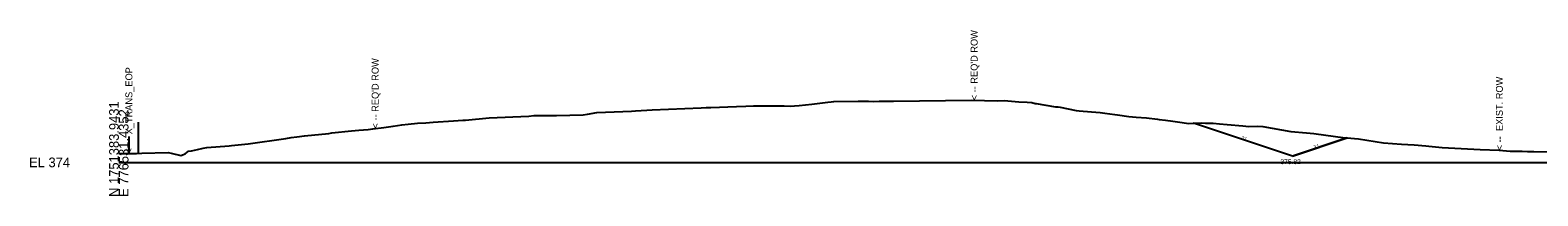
# Model space of a CAD drawing. Extents: x 776426 to 854588, y 1736205 to 1756790.
# Drawn here: x 805845.1 to 806281.9, y 1741705.1 to 1741753.1 of the extents above; entities that cross this region are included whole.
import ezdxf

# ---------------------------------------------------------------- set-up
doc = ezdxf.new("R2010")
doc.units = 0
for name, color, linetype in [('DTM CONTOURS_MAJOR_TX', 7, 'Continuous'), ('DTM_X_FLOW_ARROWS', 7, 'Continuous'), ('TRANS_EOP_PAVED', 7, 'Continuous'), ('X_TRANS_EOP', 7, 'Continuous'), ('XS_M_SHAPES_EARTHWORK', 7, 'Continuous'), ('XS_P_FINISHED_GRADE', 7, 'Continuous'), ('XS_P_ROW', 7, 'Continuous'), ('XS_P_TX_DCH', 7, 'Continuous'), ('XS_P_TX_FS_BS', 7, 'Continuous'), ('XS_X_PAVEMENT', 7, 'Continuous'), ('XS_X_ROW', 7, 'Continuous')]:
    doc.layers.add(name, color=color, linetype=linetype)

msp = doc.modelspace()

# ---------------------------------------------------------------- linework, layer by layer
at = {"layer": 'DTM CONTOURS_MAJOR_TX'}
msp.add_line((805870.79, 1741714.76), (806370.79, 1741714.76), dxfattribs=at)
at = {"layer": 'DTM_X_FLOW_ARROWS'}
msp.add_lwpolyline([(805870.79, 1741717.29), (805873.71, 1741717.31), (805875.95, 1741717.38), (805877.47, 1741717.39), (805885.04, 1741717.58), (805886, 1741717.46), (805888.72, 1741716.8), (805889.51, 1741717.02), (805889.98, 1741717.26), (805890.98, 1741717.99), (805891.84, 1741718.12), (805893.54, 1741718.48), (805895.26, 1741718.89), (805896.33, 1741719.06), (805902.78, 1741719.55), (805903.44, 1741719.62), (805908.24, 1741720.17), (805919.16, 1741721.71), (805920.75, 1741721.98), (805922.38, 1741722.17), (805924.55, 1741722.45), (805931.68, 1741723.16), (805932.49, 1741723.28), (805938.22, 1741723.87), (805940.32, 1741724.11), (805943.02, 1741724.27), (805944.35, 1741724.51), (805947.56, 1741724.84), (805950.23, 1741725.28), (805952.76, 1741725.61), (805954.67, 1741725.82), (805957.34, 1741726.08), (805959.73, 1741726.22), (805961.9, 1741726.41), (805967.74, 1741726.82), (805970.42, 1741726.99), (805971.19, 1741727.03), (805978.14, 1741727.69), (805989.63, 1741728.2), (805991, 1741728.31), (805992.42, 1741728.34), (805993, 1741728.35), (805997.61, 1741728.39), (806005.35, 1741728.53), (806006.58, 1741728.75), (806009.32, 1741729.24), (806019.3, 1741729.61), (806020.45, 1741729.67), (806022.1, 1741729.8), (806023.74, 1741729.89), (806025.33, 1741729.96), (806039.55, 1741730.6), (806040.98, 1741730.65), (806042.33, 1741730.69), (806049.8, 1741730.94), (806052.42, 1741731.03), (806054.68, 1741731.17), (806057.44, 1741731.18), (806062.26, 1741731.12), (806063.54, 1741731.11), (806065.38, 1741731.02), (806066.52, 1741731.14), (806067.9, 1741731.28), (806071.56, 1741731.62), (806076.26, 1741732.2), (806077.15, 1741732.29), (806077.94, 1741732.39), (806084.96, 1741732.49), (806087.96, 1741732.5), (806089.54, 1741732.43), (806091.12, 1741732.5), (806095.21, 1741732.52), (806117.8, 1741732.75), (806125.36, 1741732.63), (806127.32, 1741732.66), (806131.54, 1741732.32), (806133.93, 1741732.21), (806135.33, 1741732.12), (806136.27, 1741731.87), (806136.62, 1741731.8), (806142.22, 1741730.86), (806142.92, 1741730.82), (806143.52, 1741730.75), (806148.17, 1741729.8), (806149.02, 1741729.73), (806152.61, 1741729.39), (806155.14, 1741729.22), (806156.44, 1741729.02), (806159.34, 1741728.61), (806160.15, 1741728.51), (806163.43, 1741728.05), (806165.52, 1741727.83), (806168.55, 1741727.66), (806171.7, 1741727.27), (806172.19, 1741727.18), (806174.01, 1741727.01), (806176.13, 1741726.72), (806178.93, 1741726.36), (806180.68, 1741726.07), (806182.5, 1741726.14), (806184.47, 1741726.21), (806185.64, 1741726.16), (806187.87, 1741726.15), (806189.66, 1741725.9), (806191.89, 1741725.72), (806196.44, 1741725.35), (806198.2, 1741725.15), (806200.82, 1741725.28), (806202.24, 1741725.15), (806210.4, 1741723.73), (806214.92, 1741723.29), (806217, 1741723.12), (806226.09, 1741721.88), (806226.6, 1741721.85), (806230.01, 1741721.57), (806237.24, 1741720.44), (806242.4, 1741720.03), (806246.09, 1741719.87), (806249.46, 1741719.53), (806250.31, 1741719.46), (806253.23, 1741719.18), (806254.22, 1741719.04), (806265.25, 1741718.49), (806270.72, 1741718.27), (806273.91, 1741718.01), (806274.46, 1741717.99), (806277.38, 1741717.98), (806278.95, 1741717.96), (806280.8, 1741717.93), (806289.13, 1741717.86)], dxfattribs=at)
at = {"layer": 'TRANS_EOP_PAVED'}
msp.add_line((805876.39, 1741726.38), (805876.39, 1741717.38), dxfattribs=at)
msp.add_line((805876.39, 1741726.38), (805876.39, 1741717.38), dxfattribs=at)
at = {"layer": 'X_TRANS_EOP'}
msp.add_line((805873.71, 1741722.31), (805873.71, 1741717.31), dxfattribs=at)
msp.add_line((805873.71, 1741722.31), (805873.71, 1741717.31), dxfattribs=at)
at = {"layer": 'XS_M_SHAPES_EARTHWORK'}
msp.add_lwpolyline([(806210.84, 1741716.58), (806182.19, 1741726.13), (806182.5, 1741726.14), (806184.47, 1741726.21), (806185.64, 1741726.16), (806187.87, 1741726.15), (806189.66, 1741725.9), (806191.89, 1741725.72), (806196.44, 1741725.35), (806198.2, 1741725.15), (806200.82, 1741725.28), (806202.24, 1741725.15), (806210.4, 1741723.73), (806214.92, 1741723.29), (806217, 1741723.12), (806226.09, 1741721.88), (806226.6, 1741721.85), (806226.65, 1741721.85)], close=True, dxfattribs=at)
at = {"layer": 'XS_P_FINISHED_GRADE'}
for q in [(806182.19, 1741726.13), (806226.65, 1741721.85)]:
    msp.add_line((806210.84, 1741716.58), q, dxfattribs=at)

# ---------------------------------------------------------------- texts
at = {"layer": 'DTM CONTOURS_MAJOR_TX'}
for s, p in [('N 1751383.9431', (805870.79, 1741704.76)), ('E 776531.4352', (805873.59, 1741704.76))]:
    msp.add_text(s, height=2.8, rotation=90, dxfattribs=at).set_placement(p)
msp.add_text('EL 374', height=2.8, dxfattribs=at).set_placement((805844.79, 1741713.36))
at = {"layer": 'XS_P_ROW'}
for p in [(806119.61, 1741732.74), (805946.06, 1741724.59)]:
    msp.add_text("< -- REQ'D ROW", height=2, rotation=90, dxfattribs=at).set_placement(p)
at = {"layer": 'XS_P_TX_DCH'}
msp.add_text('375.82', height=1.4, dxfattribs=at).set_placement((806207.35, 1741714.25))
at = {"layer": 'XS_P_TX_FS_BS'}
for rotation, p in [(341.5651, (806196.03, 1741721.73)), (18.4349, (806217.14, 1741718.91))]:
    msp.add_text('3:1', height=0.8, rotation=rotation, dxfattribs=at).set_placement(p)
at = {"layer": 'XS_X_PAVEMENT'}
msp.add_text('< --  X_TRANS_EOP', height=2, rotation=90, dxfattribs=at).set_placement((805874.71, 1741717.31))
at = {"layer": 'XS_X_ROW'}
msp.add_text('< --  EXIST. ROW', height=2, rotation=90, dxfattribs=at).set_placement((806271.79, 1741718.27))

doc.saveas('drawing.dxf')
